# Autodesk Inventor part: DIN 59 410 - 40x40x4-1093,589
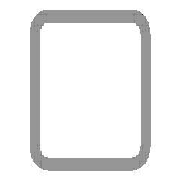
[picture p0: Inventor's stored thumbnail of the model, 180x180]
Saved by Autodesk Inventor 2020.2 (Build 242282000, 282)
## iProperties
Manager: www.cadconsulting.pl
Company: Fabian Stasiak CAD Consulting
IsCustomPart: 1
_CCFamilyMember: 20
_CCFamilyDisplayName: DIN 59410 (Kwadrat) - Rurki stalowe o przekroju kwadratowym formowane na gorąco
_FrameMemberDoc: Frame Member File
_Version: 15.0.0
_GetPNFromCC: 1
Created: 2015-01
Part Number: DIN 59 410 - 40x40x4-1093,589
Material: Stal, miękka
Description: Rurki stalowe o przekroju kwadratowym formowane na gorąco
Document SubType Name: Modellieren
Standard: DIN
Designer: F.Stasiak
Standards Organization: DIN
Language: pl-PL
Size Designation: 40x40x4
Categories: <MemberInstance><Categories><Category DisplayName="Kształtowniki konstrukcyjne" InternalName="089c4875-fa83-4c05-b084-43b9cc11f5ed" Mnemonic="GRDR"><CategoryPar
Stock Number: 40x40x4
Density: 7.85 g/cm^3
Appearance: Częściowo polerowana
Mass: 4393.44 g
Surface Area: 2813.5 cm^2
Volume: 559.674 cm^3
Catalog Web Link: www.expertbooks.pl
G_W: 40,000 mm
G_H: 40,000 mm
+6639D734-4C03-4373-B515-E3DEF9157D73+CUTDETAIL1: Wytnij
+873194C5-2EF1-4BEC-87AE-84FF10FCA1B9+CUTDETAIL2: Wytnij
G_L: 1093,589 mm
Author: F.Stasiak
Subject: Zbiór ćwiczeń. Autodesk Inventor 2020. Kurs Professional
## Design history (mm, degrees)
node "Płaszczyzna początkowa"
node "Płaszczyzna końcowa"
sketch "Szkic1"
  geometry: L1 (-12, 20)-(12, 20); L2 (20, 12)-(20, -12); L3 (12, -20)-(-12, -20); L4 (-20, -12)-(-20, 12); L5 (-30.32, 0)-(30.32, 0) reference; L6 (0, -30.32)-(0, 30.32) reference; L7 (-12, 16)-(12, 16); L8 (16, 12)-(16, -12); L9 (12, -16)-(-12, -16); L10 (-16, -12)-(-16, 12); A1 r 8 centre (-12, 12) between (-12, 20) and (-20, 12); A2 r 8 centre (12, 12) between (20, 12) and (12, 20); A3 r 8 centre (12, -12) between (12, -20) and (20, -12); A4 r 8 centre (-12, -12) between (-20, -12) and (-12, -20); A5 r 4 centre (-12, 12) between (-12, 16) and (-16, 12); A6 r 4 centre (12, 12) between (16, 12) and (12, 16); A7 r 4 centre (12, -12) between (12, -16) and (16, -12); A8 r 4 centre (-12, -12) between (-16, -12) and (-12, -16); 3 further points
  constraints: 16 end point, 16 point on circle, 8 centre point, 8 tangent, 6 point on line, 4 parallel, 3 equal radius, 3 perpendicular, 1 horizontal, 7 other
  dimensions: "b" = 40 distance of point (-20, 20) point (20, 20); "msp_r" = 8 radius of A1 (= 2 x ParT); "d8" = 20 distance between parallel lines of L4 L6 (= d9); "d9" = 20 distance between parallel lines of L3 L5 (= 0.5 x b); "d10" = 4 distance between parallel lines of L3 L9 (= ParT)
extrude "Bryła" new body sketch "Szkic1" taper "d4" = 0 deg; stored distance "NLG" = 10
node "Driven Length"
  sketch "Sketch2"
    geometry: L1 (0, 0)-(10, 0) reference
    constraints: 2 end point, 1 horizontal
  workplane "Work Plane3"
  sketch "Sketch3"
    geometry: L1 (-2, 15.355)-(12, 15.355) reference; L2 (-2, 1108.944)-(12, 1108.944) reference
    dimensions: "d14" = 1093.5891 distance between parallel lines of L1 L2 (derived)
node "Płaszczyzna konstrukcyjna4"
feature "Podział1"
node "Płaszczyzna konstrukcyjna5"
feature "Podział2"
body "Solid1"
other parameters: "ParT" = 4, "G_OFFSET_START" = -15.35534 [user parameter; used in 1 equation term], "G_OFFSET_END" = -22.42641 [user parameter; used in 1 equation term], "d11" = 15.35534 (= -G_OFFSET_START), "d12" = 1108.94444 (= G_OFFSET_END + B_L), "G_L" = 1093.5891 (= d14) [user parameter], "B_L" = 1131.37085 [user parameter; used in 1 equation term], "d13" = 90 deg
